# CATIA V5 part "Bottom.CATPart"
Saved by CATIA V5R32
Part number: Plate
Bounding box of the stored display mesh (mm): x -85 to 85, y -84.802 to 84.802, z 0 to 10
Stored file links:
  D:\PROJECTS\Project 2022\CATIA V5 6R 2022\Resources\Part Files\c12_catia_v5_6r2022_prt\c12_catia_v5-6r2022 figr_12-30\Bottom.CATPart
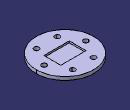
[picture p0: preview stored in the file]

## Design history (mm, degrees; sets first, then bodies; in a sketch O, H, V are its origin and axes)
Body1 (main body)
  Sketch1 on xy-plane, origin (0, 0, 0), H (1, 0, 0), V (0, 1, 0)
    circle A1 centre (0, 0) radius 85
    line L1 (37.5, 25) -> (37.5, -25)
    line L2 (37.5, -25) -> (-37.5, -25)
    line L3 (-37.5, -25) -> (-37.5, 25)
    line L4 (-37.5, 25) -> (37.5, 25)
    length L2 = 75
    length L1 = 50
    radius A1 = 85
    vertical: L1 V, L3 V
    horizontal: L2 H, L4 H
    equidistance: L1 L3 O, L2 L4 O
  MultiPad1: profile Sketch1, domains (length 5; length 10)
  Sketch2 on face of MultiPad1, origin (0, 0, 10), H (1, 0, 0), V (0, 1, 0)
    circle A1 centre (62, 0) radius 7.5
    point P1 (62, 0)
    radius A1 = 7.5
    distance P1 V = 62
    coincidence: P1 H
  Pocket1: profile Sketch2, direction (0, 0, -1), through (limit type 6)
  CircPattern1: of Pocket1, instances 6, angular step 60 {= 360.0*1 deg/CircPattern1.AngularNumber}, axis from xy-plane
